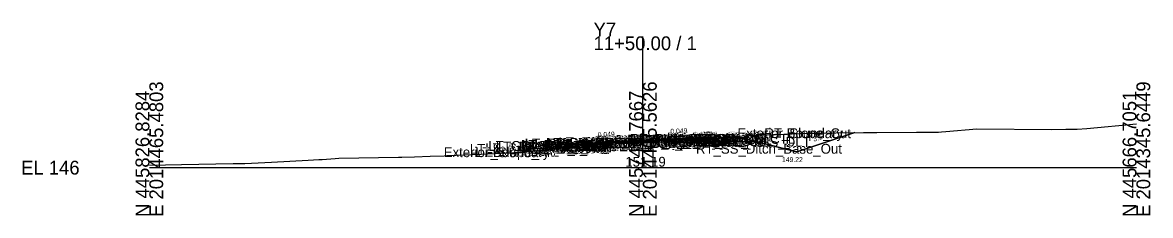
# Model space of a CAD drawing. Extents: x -26 to 203, y -10 to 7527.
# Drawn here: x -25.7 to 202.8, y 2990.3 to 3029.4 of the extents above; entities that cross this region are included whole.
import ezdxf

# ---------------------------------------------------------------- set-up
doc = ezdxf.new("R2010")
doc.units = 0
for name, color, linetype in [('Exist CMT Pavement', 7, 'Continuous'), ('Exist Cross Section Cell', 7, 'Continuous'), ('Exist XS Center Line Elevation Label', 7, 'Continuous'), ('Exist XS Ground Line', 7, 'Continuous'), ('Prop CMT Pvmt Course 1', 7, 'Continuous'), ('Prop CMT Pvmt Course 1 Wedge', 7, 'Continuous'), ('Prop CMT Pvmt Course 2', 7, 'Continuous'), ('Prop CMT Pvmt Course 2 Wedge', 7, 'Continuous'), ('Prop CMT Pvmt Course 3', 7, 'Continuous'), ('Prop CMT Pvmt Course 3 Wedge', 7, 'Continuous'), ('Prop CMT Pvmt Surface', 7, 'Continuous'), ('Prop CMT Pvmt Surface Shoulder', 7, 'Continuous'), ('Prop CMT Pvmt Wedge Surface 1', 7, 'Continuous'), ('Prop CMT Pvmt Wedge Surface 2', 7, 'Continuous'), ('Prop CMT Pvmt Wedge Surface 3', 7, 'Continuous'), ('Prop CMT Shld Paved Course 1', 7, 'Continuous'), ('Prop CMT Shld Paved Course 2', 7, 'Continuous'), ('Prop CMT Shld Paved Course 3', 7, 'Continuous'), ('Prop CMT Slope Grass', 7, 'Continuous'), ('Prop CMT Subgrade Earthwork', 7, 'Continuous'), ('Prop XS Ditch Standard Text', 7, 'Continuous'), ('Prop XS Earthwork Shape', 7, 'Continuous'), ('Prop XS SE Text', 7, 'Continuous'), ('Prop XS Side Slope Text', 7, 'Continuous'), ('Prop XS Wedging', 7, 'Continuous'), ('Scratch_Level_0', 7, 'Continuous')]:
    doc.layers.add(name, color=color, linetype=linetype)

msp = doc.modelspace()

# ---------------------------------------------------------------- linework, layer by layer
at = {"layer": 'Exist CMT Pavement'}
for points in [[(93.02, 3005.01), (93.02, 3005.01), (100, 3005.19), (100.3, 3005.2), (101.07, 3005.2), (107.56, 3005.21)], [(93.02, 3005.01), (100, 3005.19)]]:
    msp.add_lwpolyline(points, dxfattribs=at)
at = {"layer": 'Exist Cross Section Cell'}
for p, q in [((100, 3000), (100, 3026.62)), ((0, 3000), (100, 3000)), ((100, 3000), (200, 3000))]:
    msp.add_line(p, q, dxfattribs=at)
at = {"layer": 'Exist XS Ground Line'}
msp.add_lwpolyline([(0, 3000.52), (6.54, 3000.64), (17, 3000.83), (19.33, 3000.85), (24.78, 3001.13), (32.21, 3001.52), (34.37, 3001.65), (34.99, 3001.68), (36.75, 3001.81), (37.65, 3001.84), (38.39, 3001.9), (50.51, 3002.1), (50.85, 3002.1), (51.16, 3002.11), (53.69, 3002.22), (56.89, 3002.32), (59.71, 3002.41), (60.25, 3002.43), (60.7, 3002.44), (63.7, 3002.57), (67.26, 3002.71), (68.53, 3002.78), (71.3, 3002.92), (75.22, 3003.12), (75.83, 3003.15), (76.38, 3003.18), (76.97, 3003.25), (80.22, 3003.61), (88.47, 3004.5), (93.02, 3005.01), (100, 3005.19), (100.3, 3005.2), (101.07, 3005.2), (107.56, 3005.21), (108.02, 3005.28), (110.74, 3005.82), (113.73, 3004.8), (114.41, 3004.56), (114.93, 3004.57), (116.72, 3004.58), (117.96, 3006.24), (120.12, 3006.47), (131.93, 3006.95), (134.88, 3006.98), (139.08, 3007.09), (144.68, 3007.15), (146.22, 3007.15), (147.38, 3007.16), (155.41, 3007.19), (159.87, 3007.21), (160.51, 3007.24), (161.37, 3007.3), (167.65, 3007.9), (182.86, 3007.73), (185.72, 3007.81), (186.75, 3007.8), (187.98, 3007.83), (189.94, 3007.97), (200, 3008.87)], dxfattribs=at)
at = {"layer": 'Prop CMT Pvmt Course 1'}
for points in [[(100, 3005.59), (85.3, 3004.88)], [(93.02, 3005.13), (100, 3005.47)], [(100, 3005.59), (114.72, 3006.31)], [(107.56, 3005.83), (100, 3005.47)], [(100, 3005.34), (100, 3005.59)], [(100, 3005.34), (100, 3005.59)], [(100, 3005.47), (100, 3005.34), (100, 3005.34)], [(100, 3005.47), (100, 3005.34), (100, 3005.34)], [(114.72, 3006.06), (107.56, 3005.71)], [(107.56, 3005.71), (107.56, 3005.83)], [(114.72, 3006.31), (114.72, 3006.06)], [(85.3, 3004.63), (93.02, 3005)], [(85.3, 3004.88), (85.3, 3004.63)], [(93.02, 3005), (93.02, 3005.13)]]:
    msp.add_lwpolyline(points, dxfattribs=at)
at = {"layer": 'Prop CMT Pvmt Course 1 Wedge'}
for points in [[(100, 3005.47), (93.02, 3005.13)], [(100, 3005.47), (107.56, 3005.83)]]:
    msp.add_lwpolyline(points, dxfattribs=at)
at = {"layer": 'Prop CMT Pvmt Course 2'}
for points in [[(107.56, 3005.71), (114.72, 3006.06)], [(114.72, 3005.72), (107.56, 3005.38)], [(107.56, 3005.38), (107.56, 3005.71)], [(114.72, 3006.06), (114.72, 3005.72)], [(93.02, 3005), (85.3, 3004.63)], [(85.3, 3004.3), (93.02, 3004.67)], [(85.3, 3004.63), (85.3, 3004.3)], [(93.02, 3004.67), (93.02, 3005)]]:
    msp.add_lwpolyline(points, dxfattribs=at)
at = {"layer": 'Prop CMT Pvmt Course 2 Wedge'}
for points in [[(100, 3005.34), (93.02, 3005)], [(100, 3005.34), (107.56, 3005.71)]]:
    msp.add_lwpolyline(points, dxfattribs=at)
at = {"layer": 'Prop CMT Pvmt Course 3'}
for points in [[(107.56, 3005.38), (114.72, 3005.72)], [(114.72, 3005.39), (107.56, 3005.04)], [(107.56, 3005.04), (107.56, 3005.38)], [(114.72, 3005.72), (114.72, 3005.39)], [(93.02, 3004.67), (85.3, 3004.3)], [(85.3, 3003.96), (93.02, 3004.34)], [(85.3, 3004.3), (85.3, 3003.96)], [(93.02, 3004.34), (93.02, 3004.67)]]:
    msp.add_lwpolyline(points, dxfattribs=at)
at = {"layer": 'Prop CMT Pvmt Course 3 Wedge'}
for points in [[(100, 3005.01), (107.56, 3005.38)], [(100, 3005.01), (93.02, 3004.67)]]:
    msp.add_lwpolyline(points, dxfattribs=at)
at = {"layer": 'Prop CMT Pvmt Surface'}
for points in [[(100, 3005.59), (85.3, 3004.88)], [(100, 3005.59), (114.72, 3006.31)]]:
    msp.add_lwpolyline(points, dxfattribs=at)
at = {"layer": 'Prop CMT Pvmt Surface Shoulder'}
for points in [[(114.72, 3006.31), (114.72, 3006.31)], [(85.3, 3004.88), (85.3, 3004.88)]]:
    msp.add_lwpolyline(points, dxfattribs=at)
at = {"layer": 'Prop CMT Pvmt Wedge Surface 1'}
for points in [[(100, 3005.47), (93.02, 3005.13)], [(100, 3005.47), (107.56, 3005.83)], [(107.56, 3005.71), (114.72, 3006.06)], [(107.56, 3005.83), (107.56, 3005.71)], [(114.72, 3006.06), (114.72, 3006.31)], [(93.02, 3005), (85.3, 3004.63)], [(85.3, 3004.63), (85.3, 3004.88)], [(93.02, 3005.13), (93.02, 3005)]]:
    msp.add_lwpolyline(points, dxfattribs=at)
at = {"layer": 'Prop CMT Pvmt Wedge Surface 2'}
for points in [[(100, 3005.34), (85.3, 3004.63)], [(100, 3005.34), (114.72, 3006.06)], [(114.72, 3006.06), (114.72, 3006.31)], [(85.3, 3004.63), (85.3, 3004.88)]]:
    msp.add_lwpolyline(points, dxfattribs=at)
at = {"layer": 'Prop CMT Pvmt Wedge Surface 3'}
for points in [[(100, 3005.01), (114.72, 3005.72)], [(114.72, 3005.72), (114.72, 3006.31)], [(100, 3005.01), (85.3, 3004.3)], [(85.3, 3004.3), (85.3, 3004.88)]]:
    msp.add_lwpolyline(points, dxfattribs=at)
at = {"layer": 'Prop CMT Shld Paved Course 1'}
for points in [[(114.72, 3006.31), (114.72, 3006.31)], [(114.72, 3006.31), (114.98, 3006.05)], [(114.72, 3006.06), (114.72, 3006.31)], [(114.98, 3006.05), (114.72, 3006.06)], [(85.3, 3004.88), (85.05, 3004.62)], [(85.05, 3004.62), (85.3, 3004.63)], [(85.3, 3004.88), (85.3, 3004.88)], [(85.3, 3004.63), (85.3, 3004.88)]]:
    msp.add_lwpolyline(points, dxfattribs=at)
at = {"layer": 'Prop CMT Shld Paved Course 2'}
for points in [[(114.72, 3006.06), (114.98, 3006.05), (115.32, 3005.71)], [(114.72, 3005.72), (114.72, 3006.06)], [(115.32, 3005.71), (114.72, 3005.72)], [(85.3, 3004.63), (85.05, 3004.62), (84.71, 3004.28)], [(84.71, 3004.28), (85.3, 3004.3)], [(85.3, 3004.3), (85.3, 3004.63)]]:
    msp.add_lwpolyline(points, dxfattribs=at)
at = {"layer": 'Prop CMT Shld Paved Course 3'}
for points in [[(114.72, 3005.72), (114.82, 3005.72), (115.32, 3005.71), (115.66, 3005.37)], [(114.72, 3005.39), (114.72, 3005.72)], [(116.16, 3005.36), (114.72, 3005.39)], [(83.87, 3003.93), (85.3, 3003.96)], [(85.3, 3004.3), (85.21, 3004.29), (84.71, 3004.28), (84.37, 3003.94)], [(85.3, 3003.96), (85.3, 3004.3)]]:
    msp.add_lwpolyline(points, dxfattribs=at)
at = {"layer": 'Prop CMT Slope Grass'}
for points in [[(114.72, 3006.31), (120.72, 3005.83), (131.16, 3003.22)], [(131.16, 3003.22), (142.91, 3007.13)], [(85.3, 3004.88), (79.3, 3004.4), (75.5, 3003.13)]]:
    msp.add_lwpolyline(points, dxfattribs=at)
at = {"layer": 'Prop CMT Subgrade Earthwork'}
for points in [[(107.56, 3005.04), (114.72, 3005.39)], [(107.56, 3005.04), (107.56, 3005.21)], [(114.72, 3005.39), (116.16, 3005.36)], [(116.16, 3005.36), (123.14, 3005.22)], [(83.87, 3003.93), (77.53, 3003.81)], [(85.3, 3003.96), (83.87, 3003.93)], [(93.02, 3004.34), (85.3, 3003.96)], [(93.02, 3004.34), (93.02, 3005.01)]]:
    msp.add_lwpolyline(points, dxfattribs=at)
at = {"layer": 'Prop XS Earthwork Shape'}
for points in [[(107.56, 3005.04), (112.34, 3005.27), (110.74, 3005.82), (108.02, 3005.28), (107.56, 3005.21)], [(116.16, 3005.36), (117.28, 3005.34), (116.72, 3004.58), (114.93, 3004.57), (114.41, 3004.56), (113.73, 3004.8), (112.34, 3005.27), (114.72, 3005.39)], [(120.72, 3005.83), (123.14, 3005.22), (117.28, 3005.34), (117.82, 3006.06)], [(134.88, 3006.98), (139.08, 3007.09), (142.91, 3007.13), (131.16, 3003.22), (123.14, 3005.22), (120.72, 3005.83), (117.82, 3006.06), (117.96, 3006.24), (120.12, 3006.47), (131.93, 3006.95)], [(83.11, 3003.92), (77.53, 3003.81), (75.5, 3003.13), (75.83, 3003.15), (76.38, 3003.18), (76.97, 3003.25), (80.22, 3003.61)], [(83.11, 3003.92), (88.47, 3004.5), (93.02, 3005.01), (93.02, 3004.34), (85.3, 3003.96), (83.87, 3003.93)]]:
    msp.add_lwpolyline(points, close=True, dxfattribs=at)
at = {"layer": 'Prop XS Wedging'}
for p, q in [((100, 3005.47), (93.02, 3005.13)), ((93.26, 3005.02), (100, 3005.34)), ((100, 3005.34), (93.26, 3005.02)), ((107.56, 3005.83), (100, 3005.47)), ((100, 3005.47), (100, 3005.34)), ((100, 3005.34), (100, 3005.47)), ((101.69, 3005.42), (100, 3005.34)), ((101.47, 3005.21), (101.69, 3005.42)), ((101.47, 3005.21), (101.69, 3005.42)), ((101.69, 3005.42), (101.47, 3005.21)), ((101.47, 3005.21), (104.08, 3005.21)), ((107.56, 3005.71), (101.69, 3005.42)), ((104.08, 3005.21), (107.56, 3005.38)), ((107.56, 3005.38), (104.08, 3005.21)), ((104.08, 3005.21), (107.56, 3005.21)), ((107.56, 3005.71), (107.56, 3005.83)), ((107.56, 3005.38), (107.56, 3005.71)), ((107.56, 3005.21), (107.56, 3005.38)), ((93.02, 3005.13), (93.02, 3005.01)), ((93.02, 3005.01), (93.26, 3005.02)), ((93.26, 3005.02), (100, 3005.19))]:
    msp.add_line(p, q, dxfattribs=at)
for points in [[(100, 3005.34), (101.69, 3005.42), (107.56, 3005.71)], [(100, 3005.19), (100.3, 3005.2), (101.07, 3005.2), (101.47, 3005.21)]]:
    msp.add_lwpolyline(points, dxfattribs=at)

# ---------------------------------------------------------------- texts
at = {"layer": 'Exist Cross Section Cell'}
for s, p in [('Y7', (90, 3026.62)), ('11+50.00 / 1', (90, 3023.82)), ('EL 146', (-26, 2998.6))]:
    msp.add_text(s, height=2.8, dxfattribs=at).set_placement(p)
for s, p in [('E 2014465.4803', (2.8, 2990)), ('E 2014405.5626', (102.8, 2990)), ('E 2014345.6449', (202.8, 2990)), ('N 445826.8284', (0, 2990)), ('N 445746.7667', (100, 2990)), ('N 445666.7051', (200, 2990))]:
    msp.add_text(s, height=2.8, rotation=90, dxfattribs=at).set_placement(p)
at = {"layer": 'Exist XS Center Line Elevation Label'}
msp.add_text('151.19', height=2, dxfattribs=at).set_placement((96.45, 3000.19))
at = {"layer": 'Prop XS Ditch Standard Text'}
msp.add_text('149.22', height=1, dxfattribs=at).set_placement((128.18, 3001.13))
at = {"layer": 'Prop XS SE Text'}
for p in [(105.58, 3006.86), (90.87, 3006.15)]:
    msp.add_text('0.049', height=1, rotation=2.7778, dxfattribs=at).set_placement(p)
at = {"layer": 'Prop XS Side Slope Text'}
for s, rotation, p in [('3:1', 18.4332, (76.41, 3004.23)), ('4:1', 345.9638, (124.13, 3005.75)), ('3:1', 18.4349, (134.64, 3005.25))]:
    msp.add_text(s, height=1, rotation=rotation, dxfattribs=at).set_placement(p)
at = {"layer": 'Scratch_Level_0'}
for s, p in [('Exterior Boundary', (119.17, 3005.98)), ('RT_Slope_Cut', (124.62, 3005.98)), ('LT_GS_OS_CTL', (68.67, 3003.4)), ('LT_PS3_Shelf_Out', (70.19, 3003.27)), ('LT_PS3_OEOP', (74.94, 3003.28)), ('LT_PS2_OEOP', (75.28, 3003.62)), ('LT_PV2_OEOT', (75.48, 3003.63)), ('LT_PV3_OEOT', (75.48, 3003.3)), ('LT_PV1_OEOT', (76.04, 3003.88)), ('LT_PS1_OEOP', (76.11, 3003.88)), ('LT_Sub Tie Out', (80.36, 3004.01)), ('LT_PV_OEEOP_EG', (80.57, 3004.01)), ('LT_Sub_OEEOP', (82.23, 3003.34)), ('LT_PV2_OEEOP', (82.33, 3004)), ('LT_PV3_OEEOP', (82.33, 3003.67)), ('LT_PV1_OEEOP', (82.9, 3004.13)), ('RT_PV_IEEOP_EG', (88.14, 3004.19)), ('LT_PV_IEEOP_EG', (88.19, 3004.19)), ('RT_PV2_IEEOP', (89.91, 3004.34)), ('RT_PV3_IEEOP', (89.91, 3004.01)), ('LT_PV2_IEEOP', (89.95, 3004.34)), ('LT_PV3_IEEOP', (89.95, 3004.01)), ('RT_PV1_IEEOP', (90.47, 3004.47)), ('LT_PV1_IEEOP', (90.52, 3004.47)), ('PV2_PGL', (93.91, 3004.34)), ('PV1_PGL', (94.47, 3004.59)), ('RT_Sub Tie Out', (94.85, 3004.21)), ('RT_PV_OEEOP_EG', (95.06, 3004.21)), ('RT_Sub_OEEOP', (96.73, 3004.04)), ('RT_PV2_OEEOP', (96.82, 3004.71)), ('RT_PV3_OEEOP', (96.82, 3004.38)), ('RT_PV1_OEEOP', (97.39, 3004.83)), ('RT_Sub_Trench_Out', (100.31, 3004.36)), ('RT_PS3_Shelf_Out', (101.75, 3004.7)), ('RT_Sub_OEOT', (104.75, 3004.39)), ('RT_PV2_OEOT', (104.85, 3005.06)), ('RT_PV3_OEOT', (104.85, 3004.72)), ('RT_PS2_OEOP', (105.17, 3005.05)), ('RT_PV1_OEOT', (105.41, 3005.31)), ('RT_PS1_OEOP', (105.48, 3005.31)), ('RT_PS3_OEOP', (105.51, 3004.71)), ('RT_GS_OS_CTL', (110.04, 3004.83)), ('RT_Sub_OSS_DLT', (110.5, 3004.22)), ('Exterior Boundary', (59.65, 3002.13)), ('LT_Sub_OSS_DLT', (64.93, 3002.81)), ('LT_Slope_Fill', (66.02, 3002.13)), ('LT_Sub_Trench_Out', (68.07, 3002.93)), ('LT_Sub_OEOT', (75.38, 3002.96)), ('RT_SS_Ditch_Base_Out', (110.75, 3002.83))]:
    msp.add_text(s, height=2, dxfattribs=at).set_placement(p)

doc.saveas('drawing.dxf')
